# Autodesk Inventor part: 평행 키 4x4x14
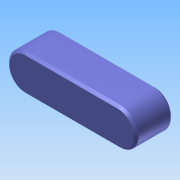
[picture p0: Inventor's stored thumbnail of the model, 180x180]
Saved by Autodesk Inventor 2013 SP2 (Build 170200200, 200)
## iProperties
Created: 2026-07
Part Number: 평행 키 4x4x14
Material: Generic
Document SubType Name: Modeling
Designer: aa
Density: 1 g/cm^3
Author: aa
변환 표준: STEP AP214IS
전처리기: Build: 200, Release: 2013 SP2 Update 6 - Date: Thu 07/17/2014
전송 단위: 밀리미터
불확실성: 0.01
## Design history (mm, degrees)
node "평행 키 4x4x141"
node "솔리드1"
node "기준1"
